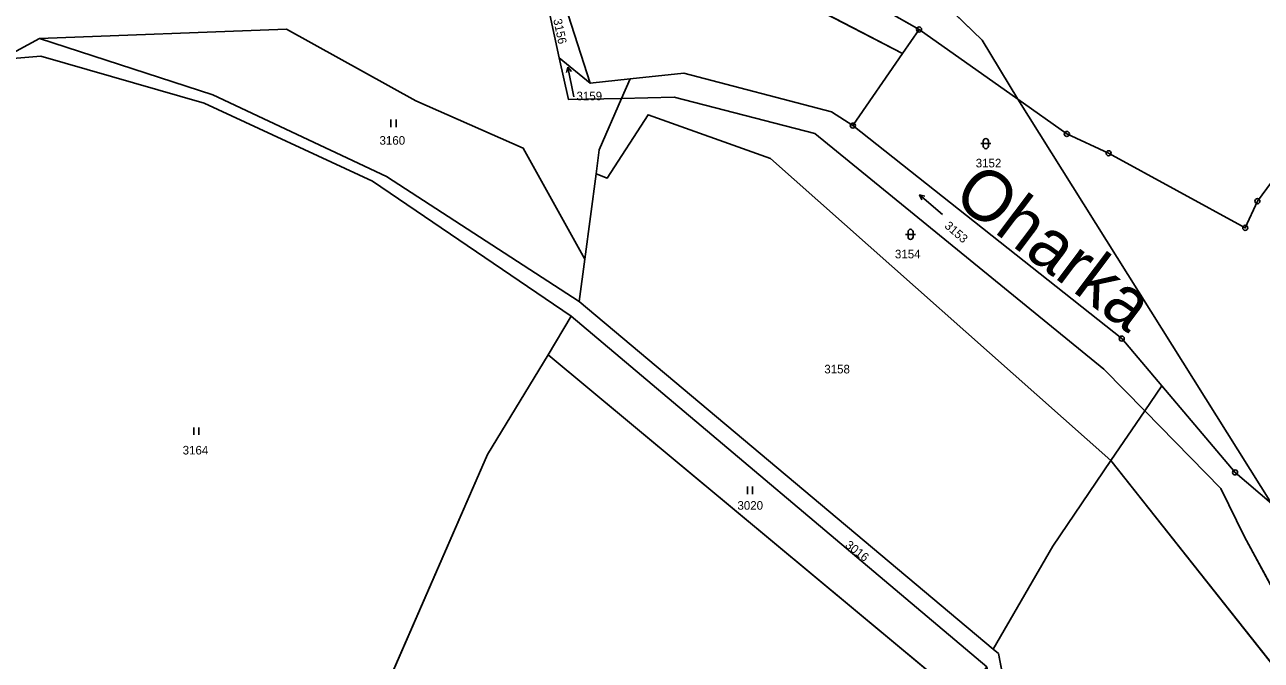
# Model space of a CAD drawing. Extents: x -689422 to -685210, y -987725 to -982160.
# Drawn here: x -688259.8 to -688015.4, y -984659.4 to -984533.7 of the extents above; entities that cross this region are included whole.
import ezdxf

# ---------------------------------------------------------------- set-up
doc = ezdxf.new("R2010")
doc.units = 0
for name, color, linetype in [('KN_Hranice_parcel', 7, 'Continuous'), ('KN_Parcelni cisla', 7, 'Continuous'), ('KN_Polygon parcely', 7, 'Continuous'), ('KN_Popisy_pomistni nazvy vodni toky', 7, 'Continuous'), ('KN_POZEMKY_ORNA PUDA', 7, 'Continuous'), ('KN_POZEMKY_OSTATNI PLOCHA', 7, 'Continuous'), ('KN_POZEMKY_TTP', 7, 'Continuous'), ('KN_POZEMKY_VODNI_PLOCHA', 7, 'Continuous'), ('KN_VYUZITI_07_vodni plocha_tok prirozeny', 7, 'Continuous'), ('KN_VYUZITI_17_ostatni plocha_ostatni komunikace', 7, 'Continuous'), ('KN_VYUZITI_27_ostatni plocha_neplodna puda', 7, 'Continuous'), ('KN_Značky bodu BP', 7, 'Continuous'), ('KN_Značky kultur', 7, 'Continuous')]:
    doc.layers.add(name, color=color, linetype=linetype)

msp = doc.modelspace()

# ---------------------------------------------------------------- linework, layer by layer
at = {"layer": 'KN_Hranice_parcel'}
for p, q in [((-688083.05, -984534.66), (-688146.21, -984498.69)), ((-688152.99, -984529.93), (-688148.04, -984545.3)), ((-688256.86, -984536.46), (-688264.46, -984540.61)), ((-688086.31, -984539.4), (-688083.05, -984534.66)), ((-688063.54, -984548.47), (-688083.05, -984534.66)), ((-688154.14, -984540.25), (-688148.04, -984545.3)), ((-688096.14, -984553.67), (-688086.31, -984539.4)), ((-688129.51, -984543.28), (-688140.16, -984544.44)), ((-688148.04, -984545.3), (-688140.16, -984544.44)), ((-688140.16, -984544.44), (-688141.83, -984548.28)), ((-688141.83, -984548.28), (-688131.44, -984548.05)), ((-688063.54, -984548.47), (-688013.44, -984628.4)), ((-688043.02, -984595.78), (-688096.14, -984553.67)), ((-688146.87, -984563.2), (-688149.12, -984580.08)), ((-688149.12, -984580.08), (-688150.23, -984588.46)), ((-688068.44, -984657.18), (-688150.23, -984588.46)), ((-688151.8, -984591.31), (-688156.32, -984598.99)), ((-688151.8, -984591.31), (-688069.67, -984660.7)), ((-688035.1, -984605.13), (-688043.02, -984595.78)), ((-688074.45, -984667.15), (-688156.32, -984598.99)), ((-688046.54, -984601.79), (-688038.45, -984610.06)), ((-688035.1, -984605.13), (-688038.45, -984610.06)), ((-688020.61, -984622.23), (-688035.1, -984605.13)), ((-688038.45, -984610.06), (-688045.14, -984619.91)), ((-688038.45, -984610.06), (-688023.42, -984625.43)), ((-688013.44, -984628.4), (-688020.61, -984622.23))]:
    msp.add_line(p, q, dxfattribs=at)
for points in [[(-688138.1, -984471.52), (-688070.62, -984536.75), (-688063.54, -984548.47)], [(-688086.31, -984539.4), (-688134.62, -984514.23), (-688132.86, -984510.47), (-688146.21, -984498.69)], [(-688158.79, -984530.17), (-688156.04, -984531.7), (-688154.14, -984540.25)], [(-688149.12, -984580.08), (-688161.28, -984558.14), (-688182.5, -984548.76), (-688208.02, -984534.57), (-688256.86, -984536.46)], [(-688150.23, -984588.46), (-688188.27, -984563.71), (-688222.59, -984547.58), (-688256.86, -984536.46)], [(-688264.46, -984540.61), (-688256.61, -984539.96), (-688224.29, -984549.22), (-688191.02, -984564.67), (-688151.8, -984591.31)], [(-688154.14, -984540.25), (-688152.3, -984548.52), (-688141.83, -984548.28)], [(-688096.14, -984553.67), (-688100.36, -984550.96), (-688129.51, -984543.28)], [(-688141.83, -984548.28), (-688146.24, -984558.47), (-688146.87, -984563.2)], [(-688131.44, -984548.05), (-688103.65, -984555.25), (-688046.54, -984601.79)], [(-687873.24, -984602.1), (-687920.07, -984592.32), (-688009.94, -984560.13), (-688016.2, -984568.61), (-688018.61, -984573.88), (-688045.6, -984559.12), (-688053.86, -984555.32), (-688063.54, -984548.47)], [(-688146.87, -984563.2), (-688144.65, -984564.03), (-688136.6, -984551.51), (-688112.44, -984560.16), (-688045.14, -984619.91)], [(-688156.32, -984598.99), (-688168.34, -984618.66), (-688190.66, -984669.91)], [(-688045.14, -984619.91), (-688056.63, -984636.83), (-688068.44, -984657.18)], [(-687916.19, -984752.61), (-687943.03, -984723.04), (-687971.08, -984702.47), (-687995.11, -984683.12), (-688045.14, -984619.91)], [(-688023.42, -984625.43), (-688018.73, -984634.98), (-688007.7, -984655.39), (-687971.46, -984694.44), (-687930.74, -984713.11), (-687915.67, -984751.84)], [(-688068.44, -984657.18), (-688067.39, -984658.06), (-688058.36, -984704.57), (-688011.98, -984748.67), (-687980.08, -984777.96), (-687957.63, -984798.89), (-687934.8, -984817.24), (-687900.91, -984840.5), (-687879.39, -984837.92), (-687841.67, -984825.09)]]:
    msp.add_lwpolyline(points, dxfattribs=at)
at = {"layer": 'KN_Polygon parcely'}
for points in [[(-688018.78, -984508.15), (-688038.77, -984497.61), (-688036.67, -984398.13), (-688063.67, -984386.89), (-688138.1, -984471.52), (-688070.62, -984536.75), (-688063.54, -984548.47), (-688053.86, -984555.32), (-688045.6, -984559.12), (-688018.61, -984573.88), (-688016.2, -984568.61), (-688009.94, -984560.13), (-687920.07, -984592.32), (-687873.24, -984602.1), (-687877.19, -984534.71), (-687980.81, -984496.41), (-687981.52, -984489.7), (-688000.34, -984479.38)], [(-688146.21, -984498.69), (-688083.05, -984534.66), (-688063.54, -984548.47), (-688070.62, -984536.75), (-688138.1, -984471.52), (-688155.6, -984491.42)], [(-688160.42, -984524.79), (-688152.99, -984529.93), (-688148.04, -984545.3), (-688140.16, -984544.44), (-688129.51, -984543.28), (-688100.36, -984550.96), (-688096.14, -984553.67), (-688086.31, -984539.4), (-688134.62, -984514.23), (-688132.86, -984510.47), (-688146.21, -984498.69), (-688156.72, -984492.7), (-688164.71, -984499.51), (-688168.43, -984497.47), (-688175.9, -984501.25), (-688170.46, -984507.28), (-688162.39, -984518.27)], [(-688146.21, -984498.69), (-688132.86, -984510.47), (-688134.62, -984514.23), (-688086.31, -984539.4), (-688083.05, -984534.66)], [(-688262.45, -984519.69), (-688262.67, -984524.58), (-688264.04, -984536.89), (-688264.46, -984540.61), (-688256.86, -984536.46), (-688208.02, -984534.57), (-688182.5, -984548.76), (-688161.28, -984558.14), (-688149.12, -984580.08), (-688146.87, -984563.2), (-688146.24, -984558.47), (-688141.83, -984548.28), (-688152.3, -984548.52), (-688154.14, -984540.25), (-688156.04, -984531.7), (-688158.79, -984530.17), (-688183.62, -984516.42), (-688200.46, -984513.91)], [(-688156.04, -984531.7), (-688154.14, -984540.25), (-688148.04, -984545.3), (-688152.99, -984529.93), (-688160.42, -984524.79), (-688158.79, -984530.17)], [(-688149.12, -984580.08), (-688161.28, -984558.14), (-688182.5, -984548.76), (-688208.02, -984534.57), (-688256.86, -984536.46), (-688222.59, -984547.58), (-688188.27, -984563.71), (-688150.23, -984588.46)], [(-688083.05, -984534.66), (-688086.31, -984539.4), (-688096.14, -984553.67), (-688043.02, -984595.78), (-688035.1, -984605.13), (-688020.61, -984622.23), (-688013.44, -984628.4), (-688063.54, -984548.47)], [(-688289.9, -984666.83), (-688208.76, -984701.04), (-688190.66, -984669.91), (-688168.34, -984618.66), (-688156.32, -984598.99), (-688151.8, -984591.31), (-688191.02, -984564.67), (-688224.29, -984549.22), (-688256.61, -984539.96), (-688264.46, -984540.61), (-688283.04, -984632.26)], [(-688141.83, -984548.28), (-688140.16, -984544.44), (-688148.04, -984545.3), (-688154.14, -984540.25), (-688152.3, -984548.52)], [(-688100.36, -984550.96), (-688129.51, -984543.28), (-688140.16, -984544.44), (-688141.83, -984548.28), (-688131.44, -984548.05), (-688103.65, -984555.25), (-688046.54, -984601.79), (-688038.45, -984610.06), (-688035.1, -984605.13), (-688043.02, -984595.78), (-688096.14, -984553.67)], [(-688144.65, -984564.03), (-688136.6, -984551.51), (-688112.44, -984560.16), (-688045.14, -984619.91), (-688038.45, -984610.06), (-688046.54, -984601.79), (-688103.65, -984555.25), (-688131.44, -984548.05), (-688141.83, -984548.28), (-688146.24, -984558.47), (-688146.87, -984563.2)], [(-688016.2, -984568.61), (-688018.61, -984573.88), (-688045.6, -984559.12), (-688053.86, -984555.32), (-688063.54, -984548.47), (-688013.44, -984628.4), (-687937.43, -984699.7), (-687907.6, -984680.54), (-687868.46, -984677.68), (-687873.24, -984602.1), (-687920.07, -984592.32), (-688009.94, -984560.13)], [(-688149.12, -984580.08), (-688150.23, -984588.46), (-688068.44, -984657.18), (-688056.63, -984636.83), (-688045.14, -984619.91), (-688112.44, -984560.16), (-688136.6, -984551.51), (-688144.65, -984564.03), (-688146.87, -984563.2)], [(-688156.32, -984598.99), (-688074.45, -984667.15), (-688069.67, -984660.7), (-688151.8, -984591.31)], [(-688074.45, -984667.15), (-688156.32, -984598.99), (-688168.34, -984618.66), (-688190.66, -984669.91), (-688116.5, -984730.66), (-688104.27, -984707.4), (-688087.23, -984684.39)], [(-687971.46, -984694.44), (-687930.74, -984713.11), (-687915.67, -984751.84), (-687911.79, -984746.13), (-687924.38, -984717.39), (-687927.64, -984709.95), (-687951.28, -984698.65), (-687967.49, -984690.91), (-688001.79, -984650.72), (-688012.43, -984630.28), (-688013.44, -984628.4), (-688020.61, -984622.23), (-688035.1, -984605.13), (-688038.45, -984610.06), (-688023.42, -984625.43), (-688018.73, -984634.98), (-688007.7, -984655.39)], [(-688038.45, -984610.06), (-688045.14, -984619.91), (-687995.11, -984683.12), (-687971.08, -984702.47), (-687943.03, -984723.04), (-687916.19, -984752.61), (-687915.67, -984751.84), (-687930.74, -984713.11), (-687971.46, -984694.44), (-688007.7, -984655.39), (-688018.73, -984634.98), (-688023.42, -984625.43)], [(-688068.44, -984657.18), (-688067.39, -984658.06), (-688058.36, -984704.57), (-688011.98, -984748.67), (-687980.08, -984777.96), (-687957.63, -984798.89), (-687934.8, -984817.24), (-687900.91, -984840.5), (-687879.39, -984837.92), (-687841.67, -984825.09), (-687849.42, -984808.57), (-687909.59, -984759.88), (-687916.19, -984752.61), (-687943.03, -984723.04), (-687971.08, -984702.47), (-687995.11, -984683.12), (-688045.14, -984619.91), (-688056.63, -984636.83)]]:
    msp.add_lwpolyline(points, close=True, dxfattribs=at)
msp.add_lwpolyline([(-688011.98, -984748.67), (-688058.36, -984704.57), (-688067.39, -984658.06), (-688068.44, -984657.18), (-688150.23, -984588.46), (-688188.27, -984563.71), (-688222.59, -984547.58), (-688256.86, -984536.46), (-688264.46, -984540.61), (-688256.61, -984539.96), (-688224.29, -984549.22), (-688191.02, -984564.67), (-688151.8, -984591.31), (-688069.67, -984660.7), (-688060.44, -984707.65), (-688014.35, -984750.56)], dxfattribs=at)
at = {"layer": 'KN_POZEMKY_ORNA PUDA'}
for p, q in [((-688070.62, -984536.75), (-688138.1, -984471.52)), ((-688063.54, -984548.47), (-688070.62, -984536.75)), ((-688013.44, -984628.4), (-688063.54, -984548.47)), ((-688063.54, -984548.47), (-688053.86, -984555.32)), ((-688053.86, -984555.32), (-688063.54, -984548.47)), ((-688144.65, -984564.03), (-688136.6, -984551.51)), ((-688136.6, -984551.51), (-688112.44, -984560.16)), ((-688053.86, -984555.32), (-688045.6, -984559.12)), ((-688045.6, -984559.12), (-688053.86, -984555.32)), ((-688112.44, -984560.16), (-688045.14, -984619.91)), ((-688045.6, -984559.12), (-688018.61, -984573.88)), ((-688018.61, -984573.88), (-688045.6, -984559.12)), ((-688016.2, -984568.61), (-688009.94, -984560.13)), ((-688009.94, -984560.13), (-688016.2, -984568.61)), ((-688149.12, -984580.08), (-688146.87, -984563.2)), ((-688146.87, -984563.2), (-688144.65, -984564.03)), ((-688018.61, -984573.88), (-688016.2, -984568.61)), ((-688016.2, -984568.61), (-688018.61, -984573.88)), ((-688150.23, -984588.46), (-688149.12, -984580.08)), ((-688068.44, -984657.18), (-688150.23, -984588.46)), ((-688045.14, -984619.91), (-688056.63, -984636.83)), ((-688056.63, -984636.83), (-688045.14, -984619.91)), ((-688045.14, -984619.91), (-687995.11, -984683.12)), ((-688056.63, -984636.83), (-688068.44, -984657.18)), ((-688068.44, -984657.18), (-688056.63, -984636.83)), ((-688067.39, -984658.06), (-688068.44, -984657.18)), ((-688058.36, -984704.57), (-688067.39, -984658.06))]:
    msp.add_line(p, q, dxfattribs=at)
at = {"layer": 'KN_POZEMKY_OSTATNI PLOCHA'}
for p, q in [((-688134.62, -984514.23), (-688086.31, -984539.4)), ((-688156.04, -984531.7), (-688154.14, -984540.25)), ((-688148.04, -984545.3), (-688152.99, -984529.93)), ((-688264.46, -984540.61), (-688256.86, -984536.46)), ((-688256.86, -984536.46), (-688264.46, -984540.61)), ((-688208.02, -984534.57), (-688256.86, -984536.46)), ((-688256.86, -984536.46), (-688222.59, -984547.58)), ((-688182.5, -984548.76), (-688208.02, -984534.57)), ((-688086.31, -984539.4), (-688083.05, -984534.66)), ((-688083.05, -984534.66), (-688063.54, -984548.47)), ((-688256.61, -984539.96), (-688264.46, -984540.61)), ((-688224.29, -984549.22), (-688256.61, -984539.96)), ((-688154.14, -984540.25), (-688152.3, -984548.52)), ((-688096.14, -984553.67), (-688086.31, -984539.4)), ((-688086.31, -984539.4), (-688096.14, -984553.67)), ((-688129.51, -984543.28), (-688140.16, -984544.44)), ((-688100.36, -984550.96), (-688129.51, -984543.28)), ((-688140.16, -984544.44), (-688148.04, -984545.3)), ((-688222.59, -984547.58), (-688188.27, -984563.71)), ((-688161.28, -984558.14), (-688182.5, -984548.76)), ((-688152.3, -984548.52), (-688141.83, -984548.28)), ((-688146.24, -984558.47), (-688141.83, -984548.28)), ((-688141.83, -984548.28), (-688146.24, -984558.47)), ((-688141.83, -984548.28), (-688131.44, -984548.05)), ((-688131.44, -984548.05), (-688103.65, -984555.25)), ((-688063.54, -984548.47), (-688013.44, -984628.4)), ((-688191.02, -984564.67), (-688224.29, -984549.22)), ((-688136.6, -984551.51), (-688144.65, -984564.03)), ((-688112.44, -984560.16), (-688136.6, -984551.51)), ((-688096.14, -984553.67), (-688100.36, -984550.96)), ((-688043.02, -984595.78), (-688096.14, -984553.67)), ((-688103.65, -984555.25), (-688046.54, -984601.79)), ((-688149.12, -984580.08), (-688161.28, -984558.14)), ((-688146.87, -984563.2), (-688146.24, -984558.47)), ((-688146.24, -984558.47), (-688146.87, -984563.2)), ((-688045.14, -984619.91), (-688112.44, -984560.16)), ((-688188.27, -984563.71), (-688150.23, -984588.46)), ((-688146.87, -984563.2), (-688149.12, -984580.08)), ((-688144.65, -984564.03), (-688146.87, -984563.2)), ((-688151.8, -984591.31), (-688191.02, -984564.67)), ((-688150.23, -984588.46), (-688068.44, -984657.18)), ((-688069.67, -984660.7), (-688151.8, -984591.31)), ((-688035.1, -984605.13), (-688043.02, -984595.78)), ((-688046.54, -984601.79), (-688038.45, -984610.06)), ((-688020.61, -984622.23), (-688035.1, -984605.13)), ((-688045.14, -984619.91), (-688038.45, -984610.06)), ((-688038.45, -984610.06), (-688045.14, -984619.91)), ((-688038.45, -984610.06), (-688023.42, -984625.43)), ((-687995.11, -984683.12), (-688045.14, -984619.91)), ((-688013.44, -984628.4), (-688020.61, -984622.23)), ((-688023.42, -984625.43), (-688018.73, -984634.98)), ((-688018.73, -984634.98), (-688007.7, -984655.39)), ((-688068.44, -984657.18), (-688067.39, -984658.06)), ((-688067.39, -984658.06), (-688058.36, -984704.57))]:
    msp.add_line(p, q, dxfattribs=at)
at = {"layer": 'KN_POZEMKY_TTP'}
for p, q in [((-688138.1, -984471.52), (-688070.62, -984536.75)), ((-688083.05, -984534.66), (-688146.21, -984498.69)), ((-688146.21, -984498.69), (-688083.05, -984534.66)), ((-688086.31, -984539.4), (-688134.62, -984514.23)), ((-688256.86, -984536.46), (-688208.02, -984534.57)), ((-688222.59, -984547.58), (-688256.86, -984536.46)), ((-688208.02, -984534.57), (-688182.5, -984548.76)), ((-688083.05, -984534.66), (-688086.31, -984539.4)), ((-688063.54, -984548.47), (-688083.05, -984534.66)), ((-688070.62, -984536.75), (-688063.54, -984548.47)), ((-688264.46, -984540.61), (-688256.61, -984539.96)), ((-688256.61, -984539.96), (-688224.29, -984549.22)), ((-688188.27, -984563.71), (-688222.59, -984547.58)), ((-688182.5, -984548.76), (-688161.28, -984558.14)), ((-688224.29, -984549.22), (-688191.02, -984564.67)), ((-688161.28, -984558.14), (-688149.12, -984580.08)), ((-688150.23, -984588.46), (-688188.27, -984563.71)), ((-688191.02, -984564.67), (-688151.8, -984591.31)), ((-688149.12, -984580.08), (-688150.23, -984588.46)), ((-688156.32, -984598.99), (-688151.8, -984591.31)), ((-688151.8, -984591.31), (-688156.32, -984598.99)), ((-688151.8, -984591.31), (-688069.67, -984660.7)), ((-688168.34, -984618.66), (-688156.32, -984598.99)), ((-688156.32, -984598.99), (-688168.34, -984618.66)), ((-688156.32, -984598.99), (-688074.45, -984667.15)), ((-688074.45, -984667.15), (-688156.32, -984598.99)), ((-688190.66, -984669.91), (-688168.34, -984618.66)), ((-688168.34, -984618.66), (-688190.66, -984669.91))]:
    msp.add_line(p, q, dxfattribs=at)
at = {"layer": 'KN_POZEMKY_VODNI_PLOCHA'}
for p, q in [((-688154.14, -984540.25), (-688156.04, -984531.7)), ((-688152.99, -984529.93), (-688148.04, -984545.3)), ((-688152.3, -984548.52), (-688154.14, -984540.25)), ((-688154.14, -984540.25), (-688148.04, -984545.3)), ((-688148.04, -984545.3), (-688154.14, -984540.25)), ((-688140.16, -984544.44), (-688129.51, -984543.28)), ((-688129.51, -984543.28), (-688100.36, -984550.96)), ((-688148.04, -984545.3), (-688140.16, -984544.44)), ((-688140.16, -984544.44), (-688141.83, -984548.28)), ((-688141.83, -984548.28), (-688140.16, -984544.44)), ((-688141.83, -984548.28), (-688152.3, -984548.52)), ((-688131.44, -984548.05), (-688141.83, -984548.28)), ((-688103.65, -984555.25), (-688131.44, -984548.05)), ((-688100.36, -984550.96), (-688096.14, -984553.67)), ((-688096.14, -984553.67), (-688043.02, -984595.78)), ((-688046.54, -984601.79), (-688103.65, -984555.25)), ((-688043.02, -984595.78), (-688035.1, -984605.13)), ((-688038.45, -984610.06), (-688046.54, -984601.79)), ((-688035.1, -984605.13), (-688038.45, -984610.06)), ((-688038.45, -984610.06), (-688035.1, -984605.13)), ((-688035.1, -984605.13), (-688020.61, -984622.23)), ((-688023.42, -984625.43), (-688038.45, -984610.06)), ((-688020.61, -984622.23), (-688013.44, -984628.4)), ((-688018.73, -984634.98), (-688023.42, -984625.43)), ((-688007.7, -984655.39), (-688018.73, -984634.98))]:
    msp.add_line(p, q, dxfattribs=at)
at = {"layer": 'KN_VYUZITI_07_vodni plocha_tok prirozeny'}
for p, q in [((-688154.14, -984540.25), (-688156.04, -984531.7)), ((-688152.99, -984529.93), (-688148.04, -984545.3)), ((-688152.3, -984548.52), (-688154.14, -984540.25)), ((-688154.14, -984540.25), (-688148.04, -984545.3)), ((-688148.04, -984545.3), (-688154.14, -984540.25)), ((-688140.16, -984544.44), (-688129.51, -984543.28)), ((-688129.51, -984543.28), (-688100.36, -984550.96)), ((-688148.04, -984545.3), (-688140.16, -984544.44)), ((-688140.16, -984544.44), (-688141.83, -984548.28)), ((-688141.83, -984548.28), (-688140.16, -984544.44)), ((-688141.83, -984548.28), (-688152.3, -984548.52)), ((-688131.44, -984548.05), (-688141.83, -984548.28)), ((-688103.65, -984555.25), (-688131.44, -984548.05)), ((-688100.36, -984550.96), (-688096.14, -984553.67)), ((-688096.14, -984553.67), (-688043.02, -984595.78)), ((-688046.54, -984601.79), (-688103.65, -984555.25)), ((-688043.02, -984595.78), (-688035.1, -984605.13)), ((-688038.45, -984610.06), (-688046.54, -984601.79)), ((-688035.1, -984605.13), (-688038.45, -984610.06)), ((-688038.45, -984610.06), (-688035.1, -984605.13)), ((-688035.1, -984605.13), (-688020.61, -984622.23)), ((-688023.42, -984625.43), (-688038.45, -984610.06)), ((-688020.61, -984622.23), (-688013.44, -984628.4)), ((-688018.73, -984634.98), (-688023.42, -984625.43)), ((-688007.7, -984655.39), (-688018.73, -984634.98))]:
    msp.add_line(p, q, dxfattribs=at)
at = {"layer": 'KN_VYUZITI_17_ostatni plocha_ostatni komunikace'}
for p, q in [((-688264.46, -984540.61), (-688256.86, -984536.46)), ((-688256.86, -984536.46), (-688222.59, -984547.58)), ((-688256.61, -984539.96), (-688264.46, -984540.61)), ((-688224.29, -984549.22), (-688256.61, -984539.96)), ((-688222.59, -984547.58), (-688188.27, -984563.71)), ((-688191.02, -984564.67), (-688224.29, -984549.22)), ((-688188.27, -984563.71), (-688150.23, -984588.46)), ((-688151.8, -984591.31), (-688191.02, -984564.67)), ((-688150.23, -984588.46), (-688068.44, -984657.18)), ((-688069.67, -984660.7), (-688151.8, -984591.31)), ((-688068.44, -984657.18), (-688067.39, -984658.06)), ((-688067.39, -984658.06), (-688058.36, -984704.57))]:
    msp.add_line(p, q, dxfattribs=at)
at = {"layer": 'KN_VYUZITI_27_ostatni plocha_neplodna puda'}
for p, q in [((-688134.62, -984514.23), (-688086.31, -984539.4)), ((-688156.04, -984531.7), (-688154.14, -984540.25)), ((-688148.04, -984545.3), (-688152.99, -984529.93)), ((-688256.86, -984536.46), (-688264.46, -984540.61)), ((-688208.02, -984534.57), (-688256.86, -984536.46)), ((-688182.5, -984548.76), (-688208.02, -984534.57)), ((-688086.31, -984539.4), (-688083.05, -984534.66)), ((-688083.05, -984534.66), (-688063.54, -984548.47)), ((-688154.14, -984540.25), (-688152.3, -984548.52)), ((-688096.14, -984553.67), (-688086.31, -984539.4)), ((-688086.31, -984539.4), (-688096.14, -984553.67)), ((-688129.51, -984543.28), (-688140.16, -984544.44)), ((-688100.36, -984550.96), (-688129.51, -984543.28)), ((-688140.16, -984544.44), (-688148.04, -984545.3)), ((-688161.28, -984558.14), (-688182.5, -984548.76)), ((-688152.3, -984548.52), (-688141.83, -984548.28)), ((-688146.24, -984558.47), (-688141.83, -984548.28)), ((-688141.83, -984548.28), (-688146.24, -984558.47)), ((-688141.83, -984548.28), (-688131.44, -984548.05)), ((-688131.44, -984548.05), (-688103.65, -984555.25)), ((-688063.54, -984548.47), (-688013.44, -984628.4)), ((-688136.6, -984551.51), (-688144.65, -984564.03)), ((-688112.44, -984560.16), (-688136.6, -984551.51)), ((-688096.14, -984553.67), (-688100.36, -984550.96)), ((-688043.02, -984595.78), (-688096.14, -984553.67)), ((-688103.65, -984555.25), (-688046.54, -984601.79)), ((-688149.12, -984580.08), (-688161.28, -984558.14)), ((-688146.87, -984563.2), (-688146.24, -984558.47)), ((-688146.24, -984558.47), (-688146.87, -984563.2)), ((-688045.14, -984619.91), (-688112.44, -984560.16)), ((-688146.87, -984563.2), (-688149.12, -984580.08)), ((-688144.65, -984564.03), (-688146.87, -984563.2)), ((-688035.1, -984605.13), (-688043.02, -984595.78)), ((-688046.54, -984601.79), (-688038.45, -984610.06)), ((-688020.61, -984622.23), (-688035.1, -984605.13)), ((-688045.14, -984619.91), (-688038.45, -984610.06)), ((-688038.45, -984610.06), (-688045.14, -984619.91)), ((-688038.45, -984610.06), (-688023.42, -984625.43)), ((-687995.11, -984683.12), (-688045.14, -984619.91)), ((-688013.44, -984628.4), (-688020.61, -984622.23)), ((-688023.42, -984625.43), (-688018.73, -984634.98)), ((-688018.73, -984634.98), (-688007.7, -984655.39))]:
    msp.add_line(p, q, dxfattribs=at)
at = {"layer": 'KN_Značky bodu BP'}
for centre, radius in [((-688083.05, -984534.66), 0.5), ((-688083.05, -984534.66), 0.0303), ((-688096.14, -984553.67), 0.5), ((-688096.14, -984553.67), 0.0303), ((-688053.86, -984555.32), 0.5), ((-688053.86, -984555.32), 0.0303), ((-688045.6, -984559.12), 0.5), ((-688045.6, -984559.12), 0.0303), ((-688016.2, -984568.61), 0.5), ((-688016.2, -984568.61), 0.0303), ((-688018.61, -984573.88), 0.5), ((-688018.61, -984573.88), 0.0303), ((-688043.02, -984595.78), 0.5), ((-688043.02, -984595.78), 0.0303), ((-688020.61, -984622.23), 0.5), ((-688020.61, -984622.23), 0.0303)]:
    msp.add_circle(centre, radius, dxfattribs=at)
at = {"layer": 'KN_Značky kultur'}
for p, q in [((-688152.44, -984542.1), (-688152.74, -984543.15)), ((-688151.29, -984547.99), (-688152.44, -984542.1)), ((-688152.44, -984542.1), (-688151.76, -984542.96)), ((-688187.4, -984553.95), (-688187.4, -984552.45)), ((-688186.4, -984553.95), (-688186.4, -984552.45)), ((-688070.86, -984557.23), (-688068.86, -984557.23)), ((-688070.36, -984556.73), (-688070.36, -984557.73)), ((-688069.36, -984557.73), (-688069.36, -984556.73)), ((-688078.42, -984571.26), (-688082.95, -984567.32)), ((-688082.95, -984567.32), (-688082.54, -984568.34)), ((-688082.95, -984567.32), (-688081.89, -984567.59)), ((-688085.74, -984575.17), (-688083.74, -984575.17)), ((-688085.24, -984574.67), (-688085.24, -984575.67)), ((-688084.24, -984575.67), (-688084.24, -984574.67)), ((-688226.37, -984614.83), (-688226.37, -984613.33)), ((-688225.37, -984614.83), (-688225.37, -984613.33)), ((-688116.98, -984626.52), (-688116.98, -984625.02)), ((-688115.98, -984626.52), (-688115.98, -984625.02))]:
    msp.add_line(p, q, dxfattribs=at)
for centre, start, end in [((-688069.86, -984556.73), 0, 180), ((-688069.86, -984557.73), 180, 359.9879), ((-688084.74, -984574.67), 0, 180), ((-688084.74, -984575.67), 180, 359.9879)]:
    msp.add_arc(centre, 0.5, start, end, dxfattribs=at)

# ---------------------------------------------------------------- texts
at = {"layer": 'KN_Parcelni cisla'}
for s, rotation, p in [('3156', 282, (-688155.34, -984532.72)), ('3153', 319, (-688078.16, -984573.7)), ('3016', 322, (-688097.8, -984636.88))]:
    msp.add_text(s, height=1.7, rotation=rotation, dxfattribs=at).set_placement(p)
for s, p in [('3159', (-688150.74, -984548.66)), ('3160', (-688189.66, -984557.44)), ('3152', (-688071.86, -984561.93)), ('3154', (-688087.82, -984579.91)), ('3158', (-688101.78, -984602.66)), ('3164', (-688228.56, -984618.69)), ('3020', (-688118.94, -984629.61))]:
    msp.add_text(s, height=1.7, dxfattribs=at).set_placement(p)
at = {"layer": 'KN_Popisy_pomistni nazvy vodni toky'}
msp.add_text('Oharka', height=10, rotation=323.0457, dxfattribs=at).set_placement((-688076.74, -984568.43))

doc.saveas('drawing.dxf')
